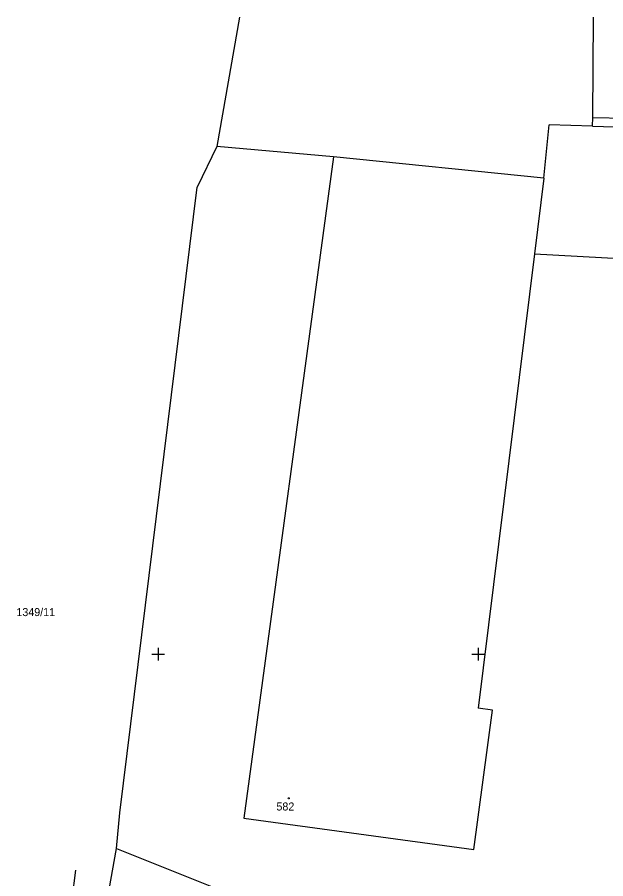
# Model space of a CAD drawing. Extents: x -866624 to -866276, y -1050208 to -1049940.
# Drawn here: x -866448.8 to -866412, y -1049994 to -1049940.2 of the extents above; entities that cross this region are included whole.
import ezdxf

# ---------------------------------------------------------------- set-up
doc = ezdxf.new("R2010")
doc.units = 0
for name, color, linetype in [('CTV-SIT', 7, 'Continuous'), ('Default', 7, 'Continuous'), ('HRAN-LIN', 7, 'Continuous'), ('Hranice', 7, 'Continuous'), ('Hranice další', 7, 'Continuous'), ('Hranice-budov', 7, 'Continuous'), ('Parcela-pozemkova', 7, 'Continuous'), ('Parcela-stavebni', 7, 'Continuous'), ('znacky-budov', 7, 'Continuous')]:
    doc.layers.add(name, color=color, linetype=linetype)

# ---------------------------------------------------------------- blocks, each defined once
blk = doc.blocks.new('s_zdena')
at = {"layer": 'Default'}
blk.add_circle((0, 0), 0.175, dxfattribs=at)
for start, end in [(0, 180), (180, 0)]:
    blk.add_arc((0, 0), 0.0875, start, end, dxfattribs=at)
blk = doc.blocks.new('CTVSIT')
at = {"layer": 'Default'}
for p, q in [((-2, 0), (2, 0)), ((0, 2), (0, -2))]:
    blk.add_line(p, q, dxfattribs=at)

msp = doc.modelspace()

# ---------------------------------------------------------------- linework, layer by layer
at = {"layer": 'HRAN-LIN'}
msp.add_line((-866445.172, -1049993.49), (-866448.79, -1050022.02), dxfattribs=at)
at = {"layer": 'Hranice'}
for p, q in [((-866434.913, -1049940.226), (-866436.33, -1049948.3)), ((-866412.83, -1049946.48), (-866412.787, -1049940.226)), ((-866412.84, -1049947.03), (-866412.83, -1049946.48)), ((-866412.83, -1049946.48), (-866371.52, -1049947.46)), ((-866415.89, -1049950.28), (-866415.55, -1049946.95)), ((-866412.84, -1049947.03), (-866415.55, -1049946.95)), ((-866436.33, -1049948.3), (-866437.55, -1049950.84)), ((-866415.89, -1049950.28), (-866416.48, -1049955)), ((-866442.4, -1049989.9), (-866437.55, -1049950.84)), ((-866416.48, -1049955), (-866371.93, -1049957.4)), ((-866442.6, -1049992.13), (-866442.4, -1049989.9)), ((-866447.95, -1050021.71), (-866442.6, -1049992.13)), ((-866442.6, -1049992.13), (-866435, -1049995.17))]:
    msp.add_line(p, q, dxfattribs=at)
at = {"layer": 'Hranice další'}
for p, q in [((-866412.84, -1049947.03), (-866390.81, -1049947.65)), ((-866429.03, -1049948.94), (-866436.33, -1049948.3)), ((-866429.03, -1049948.94), (-866434.64, -1049990.24)), ((-866415.89, -1049950.28), (-866429.03, -1049948.94)), ((-866416.48, -1049955), (-866419.99, -1049983.37)), ((-866420.27, -1049992.19), (-866419.09, -1049983.49)), ((-866419.09, -1049983.49), (-866419.99, -1049983.37)), ((-866434.64, -1049990.24), (-866420.27, -1049992.19))]:
    msp.add_line(p, q, dxfattribs=at)
at = {"layer": 'Hranice-budov'}
for p, q in [((-866415.89, -1049950.28), (-866415.55, -1049946.95)), ((-866412.84, -1049947.03), (-866415.55, -1049946.95)), ((-866412.84, -1049947.03), (-866390.81, -1049947.65)), ((-866429.03, -1049948.94), (-866434.64, -1049990.24)), ((-866415.89, -1049950.28), (-866429.03, -1049948.94)), ((-866415.89, -1049950.28), (-866416.48, -1049955)), ((-866415.89, -1049950.28), (-866416.48, -1049955)), ((-866416.48, -1049955), (-866419.99, -1049983.37)), ((-866416.48, -1049955), (-866371.93, -1049957.4)), ((-866420.27, -1049992.19), (-866419.09, -1049983.49)), ((-866419.09, -1049983.49), (-866419.99, -1049983.37)), ((-866434.64, -1049990.24), (-866420.27, -1049992.19))]:
    msp.add_line(p, q, dxfattribs=at)

# ---------------------------------------------------------------- block references
at = {"layer": 'CTV-SIT', "xscale": 0.19999999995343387, "yscale": 0.19999999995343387}
for p in [(-866440, -1049980), (-866420, -1049980)]:
    msp.add_blockref('CTVSIT', p, dxfattribs=at)
at = {"layer": 'znacky-budov', "xscale": 0.2, "yscale": 0.20000000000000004}
msp.add_blockref('s_zdena', (-866431.833, -1049989.004), dxfattribs=at)

# ---------------------------------------------------------------- texts
at = {"layer": 'Parcela-pozemkova'}
msp.add_text('1349/11', height=0.5, dxfattribs=at).set_placement((-866448.856, -1049977.623))
at = {"layer": 'Parcela-stavebni'}
msp.add_text('582', height=0.5, dxfattribs=at).set_placement((-866432.604, -1049989.764))

doc.saveas('drawing.dxf')
